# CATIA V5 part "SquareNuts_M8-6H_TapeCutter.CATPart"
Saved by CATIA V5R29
Part number: SquareNuts_M8-6H_TapeCutter
Source: Unknown
Bounding box of the stored display mesh (mm): x -7 to 7, y -7 to 7, z -3 to 3
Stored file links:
  C:\가치같이\SmartFactory_BoxErectorConveyor\Boxing(under)\SquareNuts_M8-6H_TapeCutter.CATPart
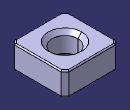
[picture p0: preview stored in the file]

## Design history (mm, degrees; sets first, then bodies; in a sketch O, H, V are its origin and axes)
Body1 (main body)
  Solid1 "PartBody": solid without history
